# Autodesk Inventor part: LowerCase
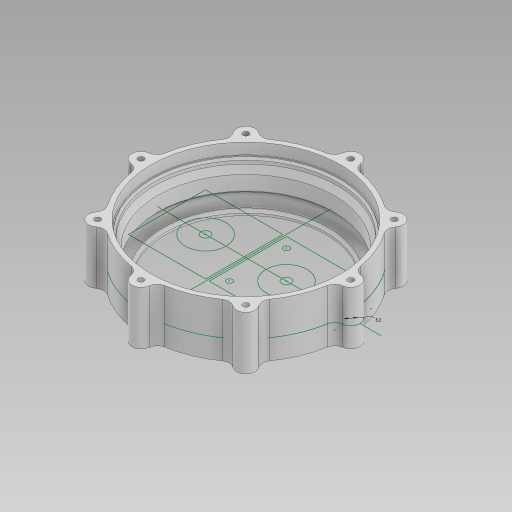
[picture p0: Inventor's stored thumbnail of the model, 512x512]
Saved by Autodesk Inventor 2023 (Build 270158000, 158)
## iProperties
Created: 2024-05
Part Number: LowerCase
Material: 一般
Document SubType Name: Modeling
Designer: kumagai
Density: 1 g/cm^3
Appearance: 既定
Author: kumagai
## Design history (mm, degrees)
derived "CoreSketch.ipt"
  sketch "Vertical"
    geometry: L1 (0, 65.337)-(0, -65.337) reference; L2 (-46.2, 0)-(46.2, 0) reference; L3 (-11, 2)-(11, 2) reference; L4 (11, 2)-(11, -2) reference; L5 (11, -2)-(-11, -2) reference; L6 (-11, -2)-(-11, 2) reference; L7 (11, 2)-(33, 2) reference; L8 (33, 2)-(33, -2) reference; L9 (33, -2)-(11, -2) reference; L10 (11, -2)-(11, 2) reference; L11 (22, 2.772)-(22, -2.683) reference; L12 (-33, 2)-(-11, 2) reference; L13 (-11, 2)-(-11, -2) reference; L14 (-11, -2)-(-33, -2) reference; L15 (-33, -2)-(-33, 2) reference; L16 (-22, 4.087)-(-22, -4.199) reference; L17 (-33, 10)-(-11, 10) reference; L18 (-11, 10)-(-11, 6) reference; L19 (-11, 6)-(-33, 6) reference; L20 (-33, 6)-(-33, 10) reference; L21 (-27.353, 10)-(-16.647, 10) reference; L22 (-16.647, 10)-(-16.647, 16) reference; L23 (-16.647, 16)-(-27.353, 16) reference; L24 (-27.353, 16)-(-27.353, 10) reference; L25 (11, 16)-(33, 16) reference; L26 (33, 16)-(33, 12) reference; L27 (33, 12)-(11, 12) reference; L28 (11, 12)-(11, 16) reference; L29 (16.134, 12)-(27.866, 12) reference; L30 (27.866, 12)-(27.866, 6) reference; L31 (27.866, 6)-(16.134, 6) reference; L32 (16.134, 6)-(16.134, 12) reference; L33 (-22, 18.272)-(-22, 9.031) reference; L34 (22, 22.635)-(22, 12.71) reference; L35 (33, -2)-(35, -2) reference; L36 (35, -2)-(35, 10) reference; L37 (35, 10)-(33, 10) reference; L38 (33, 10)-(33, -2) reference; L39 (0, -4)-(37.5, -4) reference; L40 (40.5, -1)-(40.5, 14) reference; L41 (43.9, -8)-(0, -8) reference; L42 (0, -4)-(0, -8) reference; L43 (35, -2)-(39, -2) reference; L44 (39, -2)-(39, 3.066) reference; L45 (38.45, 8.685)-(41.471, 10.429) reference; L46 (38.45, 10)-(35, 10) reference; L47 (40.5, 9.627)-(41.993, 8.375) reference; L48 (41.55, 3.315)-(40.5, 2.709) reference; L49 (37.5, -4)-(40.5, -1) reference; L50 (-43, 43.294)-(-1, 43.294) reference; L51 (-1, 43.294)-(-1, 26) reference; L52 (-1, 26)-(-43, 26) reference; L53 (-43, 26)-(-43, 43.294) reference; L54 (1, 43.294)-(43, 43.294) reference; L55 (43, 43.294)-(43, 26) reference; L56 (43, 26)-(1, 26) reference; L57 (1, 26)-(1, 43.294) reference; L58 (-22, 45.556)-(-22, 31.232) reference; L59 (22, 47.214)-(22, 32.287) reference; L60 (48, 5.268)-(48, -2.616) reference; L61 (43.6, -11)-(54, -11) reference; L62 (54, -11)-(54, 18) reference; L63 (45.222, -3.461)-(46.5, -2.566) reference; L64 (48, -2.616)-(49.192, -3.808) reference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; A1 r 3.1 centre (40, 6) between (39, 3.066) and (38.45, 8.685) reference; A2 r 3.1 centre (47, -6) between (45.222, -3.461) and (49.192, -3.808) reference; A3 r 3.1 centre (47, 13) between (43.9, 13) and (49, 10.631) reference; 2 further points; 1 other entity
    constraints: 1 other
  sketch "OuterLayout"
    geometry: L1 (0, -46.2)-(0, 46.2) reference; L2 (-73.4, 0)-(62.4, 0) reference; L3 (43, -21)-(1, -21) reference; L4 (1, -21)-(1, 21) reference; L5 (1, 21)-(43, 21) reference; L6 (43, 21)-(43, -21) reference; L7 (-1, -21)-(-43, -21) reference; L8 (-43, -21)-(-43, 21) reference; L9 (-43, 21)-(-1, 21) reference; L10 (-1, 21)-(-1, -21) reference; C1 r 11.1 at (22, 0) reference; C2 r 11.1 at (-22, 0) reference; C3 r 2.5 at (-22, 0) reference; C4 r 2.5 at (22, 0) reference; C5 r 1.6 at (-6.5, -15.5) reference; C6 r 1.6 at (-37.5, -15.5) reference; C7 r 1.6 at (-6.5, 15.5) reference; C8 r 1.6 at (-37.5, 15.5) reference; C9 r 51.5 at (0, 0) reference; C10 r 1.6 at (-57, 0) reference; A1 r 54 centre (0, 0) between (-53.229, -9.091) and (-53.229, 9.091) reference; A2 r 5 centre (-58.158, -9.933) between (-53.229, -9.091) and (-57.579, -4.966) reference; A3 r 5 centre (-58.158, 9.933) between (-57.579, 4.966) and (-53.229, 9.091) reference; A4 r 5 centre (-57, 0) between (-53.86, 3.891) and (-53.86, -3.891) reference; 1 further point
revolve "回転1" stored, may be unused: angle "d1" = 360 deg
sketch "スケッチ3"
  geometry: C1 r 1.6 at (-57, 0) reference; C2 r 2.65 at (-57, 0); A1 r 5 centre (-57, 0) between (-53.86, 3.891) and (-53.86, -3.891) reference; A2 r 5 centre (-58.158, 9.933) between (-57.579, 4.966) and (-53.229, 9.091) reference; A3 r 5 centre (-58.158, -9.933) between (-53.229, -9.091) and (-57.579, -4.966) reference; A4 r 54 centre (0, 0) between (-53.86, 3.891) and (-53.86, -3.891) reference; 1 further point
  constraints: 1 centre point, 1 coincident
  dimensions: "d2" = 5.3 diameter of C2
extrude "押し出し1" join sketch "スケッチ3" stored distance "d3" = 10; taper "d4" = 0 deg
extrude "押し出し2" cut sketch "スケッチ3" stored distance "d5" = 13; taper "d6" = 0 deg
chamfer "面取り1" distance "d7" = 1; stored, may be unused: second distance "d8" = 2, angle "d9" = 45 deg
pattern_circular "円形状パターン1" dims angle "d11" = 360 deg
node "ソリッド1"
